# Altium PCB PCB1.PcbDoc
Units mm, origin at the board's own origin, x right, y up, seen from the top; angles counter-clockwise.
Board outline 77.6 x 45.97 mm, 2 copper layers (Top Layer, Bottom Layer); 10 components, 6 nets, 87 pads, 0 vias.
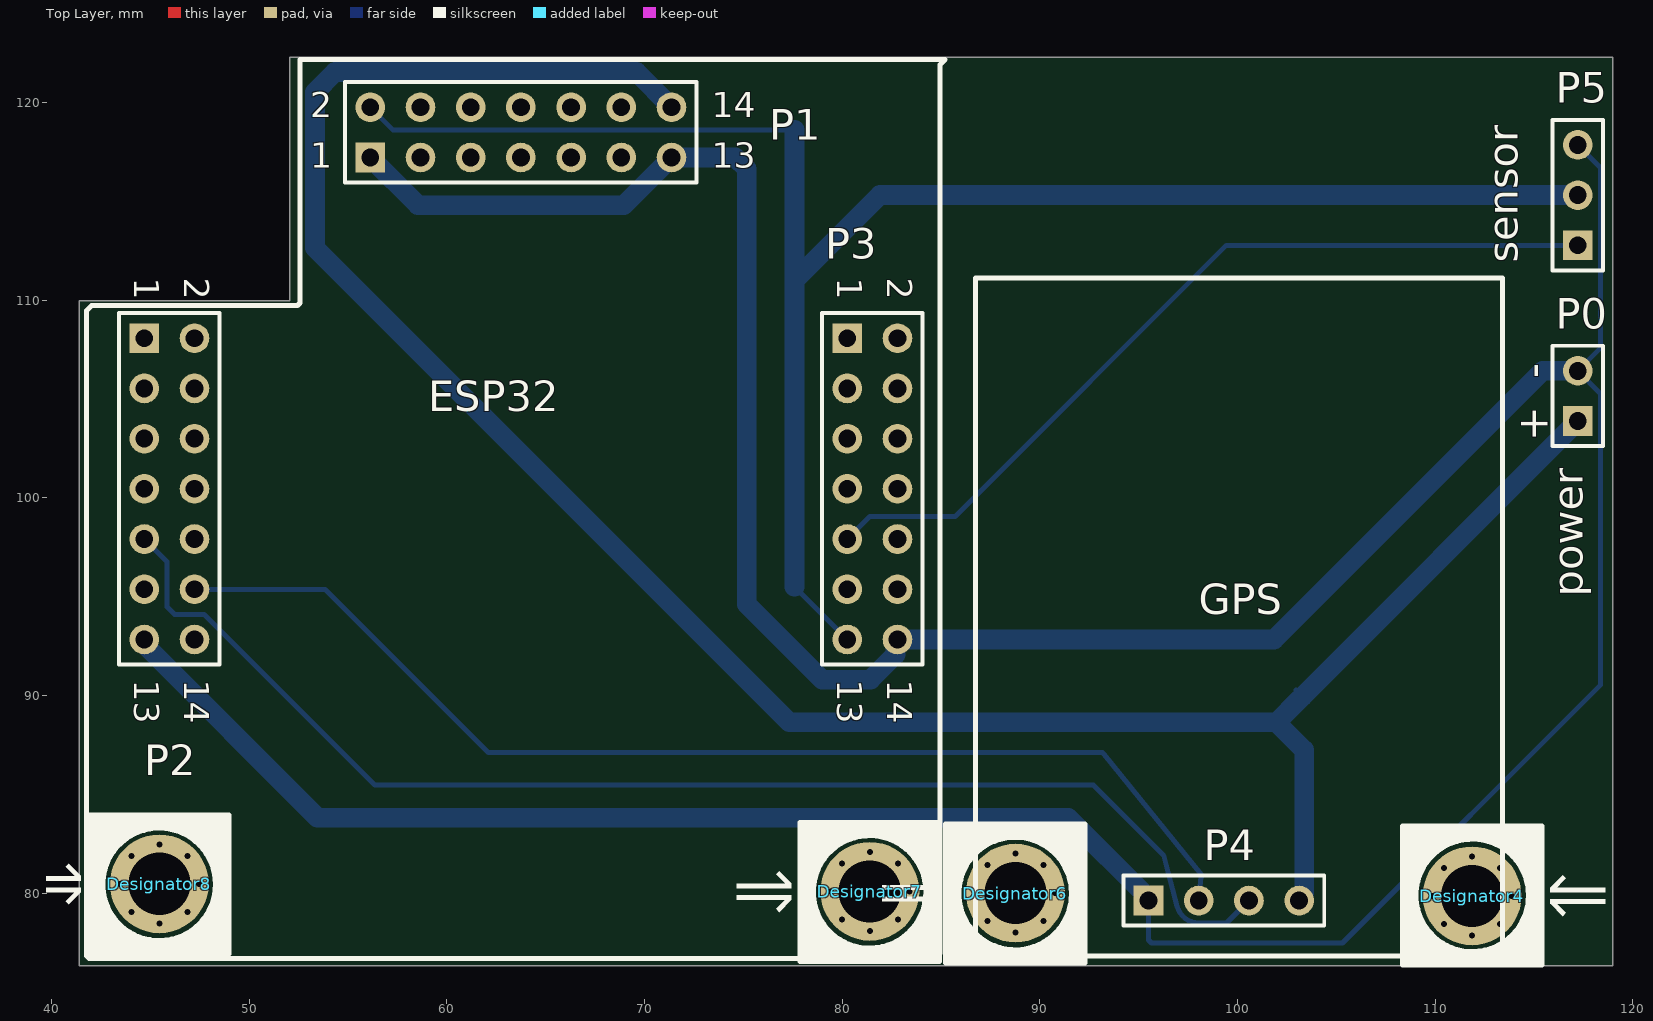
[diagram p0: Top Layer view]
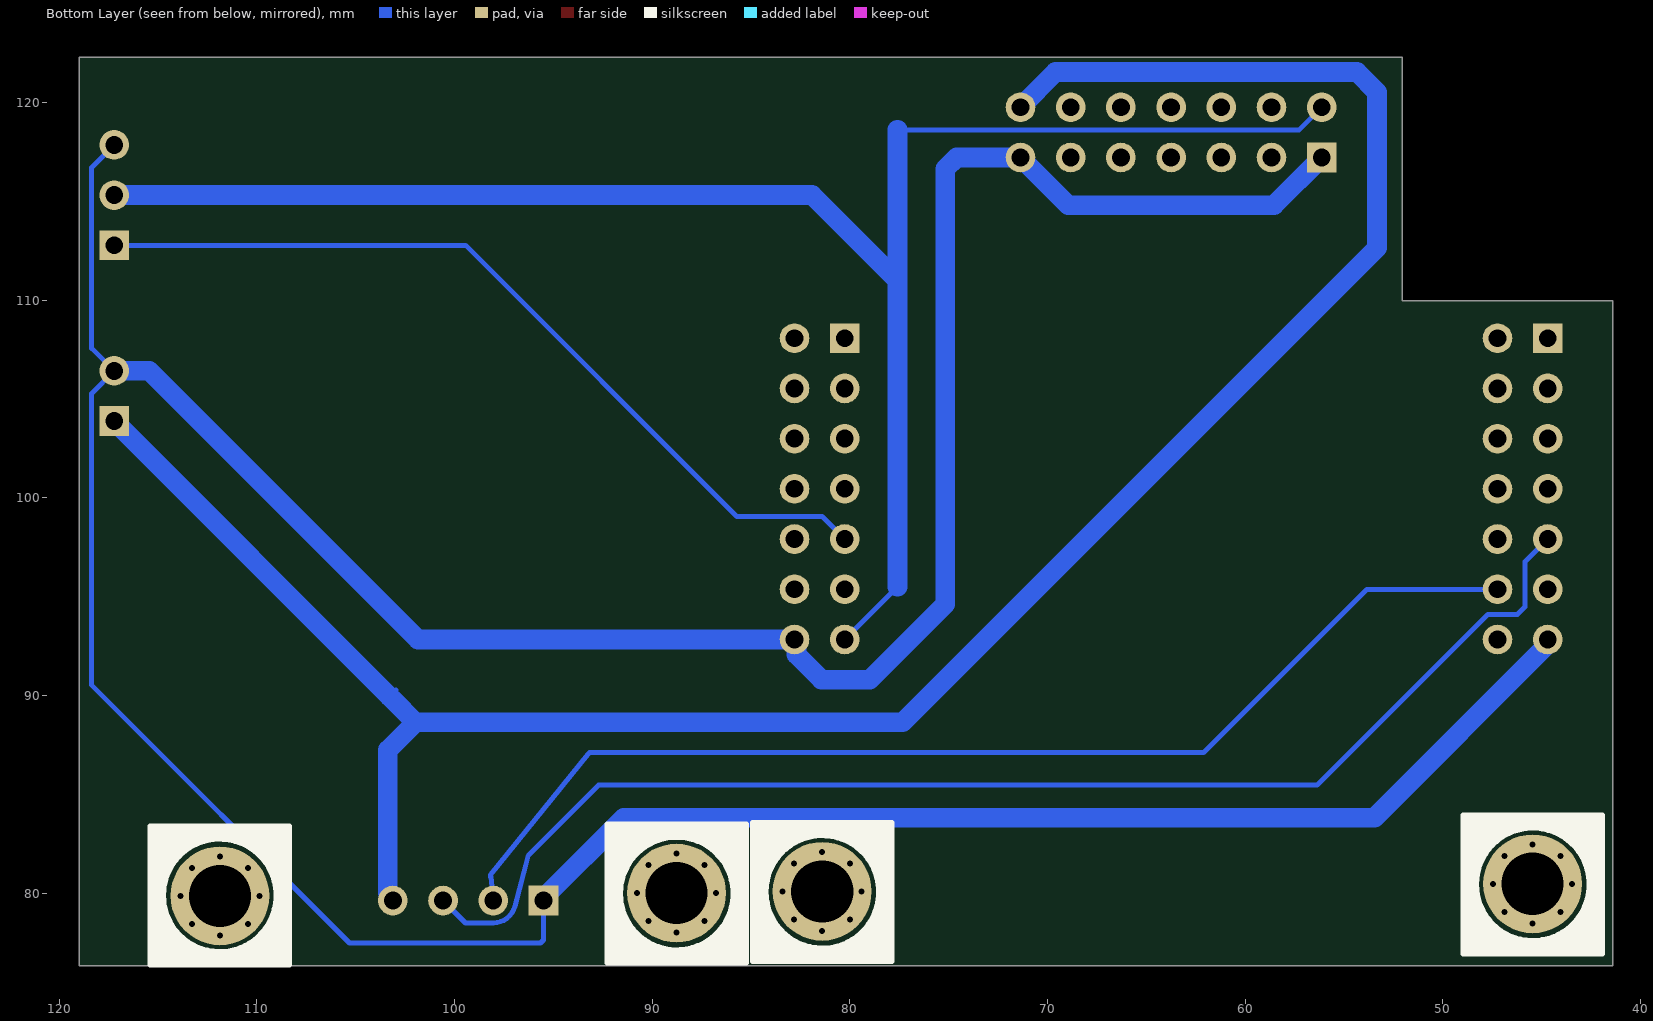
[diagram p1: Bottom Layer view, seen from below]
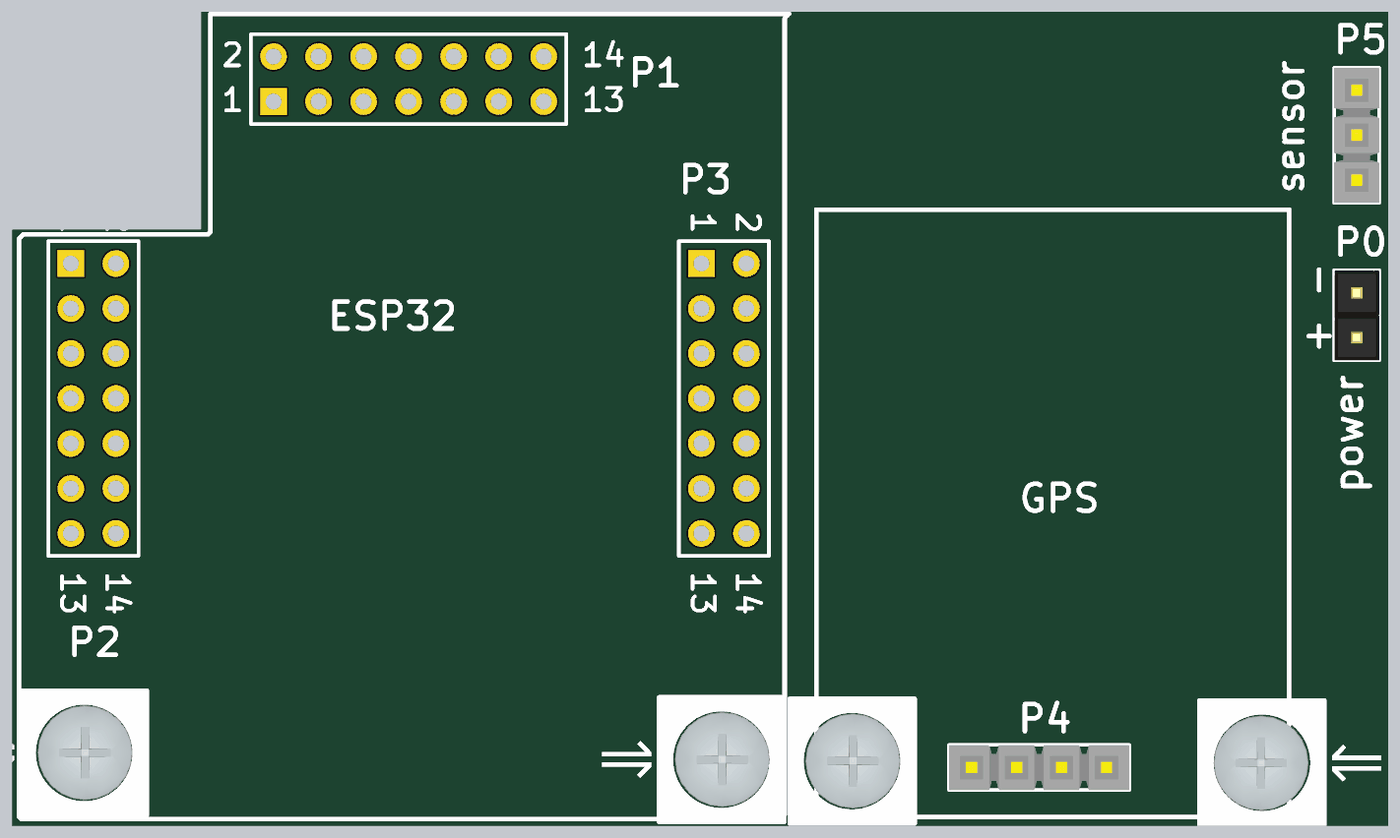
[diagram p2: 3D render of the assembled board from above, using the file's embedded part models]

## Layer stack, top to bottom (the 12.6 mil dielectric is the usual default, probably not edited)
Top Solder: solder mask 0.0102, Solder Resist, Dk 3.5
Top Layer: signal copper 0.0356
Dielectric 1: dielectric 0.32, FR-4, Dk 4.8
Bottom Layer: signal copper 0.0356
Bottom Solder: solder mask 0.0102, Solder Resist, Dk 3.5

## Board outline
41.402,76.327 41.402,109.982 52.07,109.982 52.07,122.301 118.999,122.301 118.999,76.327

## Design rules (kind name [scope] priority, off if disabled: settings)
Clearance [All] p1: gap=0.254 ignorepadtopadclearanceinfootprint=FALSE
PolygonConnect [All] p1: connectstyle=Relief reliefconductorwidth=0.254 reliefentries=4 polygonreliefangle="90 Angle" airgapwidth=0.254
RoutingVias [All] p1: holewidth=0.711 width=1.27 viastyle="Through Hole" minholewidth=0.711 minwidth=1.27 maxholewidth=0.711 maxwidth=1.27
SolderMaskExpansion [All] p1: expansion=0.102 istentingtop=FALSE
SupplyNets "Schematic Supply Nets_2" [InNet('VCC')] p1: voltage=0.000
SupplyNets "Schematic Supply Nets_1" [InNet('GND')] p2: voltage=0.000
SupplyNets "Schematic Supply Nets" [InNet('3.3v')] p3: voltage=0.000
Width [All] p1: maxlimit=2 minlimit=0.254 preferedwidth=1 minimp=50.000000 maximp=50.000000 favimp=50.000000
30 further rules are at their usual default settings.

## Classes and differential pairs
component class Sheet1: P0 P1 P2 P3 P4 P5

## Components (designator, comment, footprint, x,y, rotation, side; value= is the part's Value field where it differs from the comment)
Designator4 "Comment" "Board Screw" 111.87,79.866 r90 top
Designator6 "Comment" "Board Screw" 88.773,80.01 r270 top
Designator7 "Comment" "Board Screw" 81.407,80.093 r270 top
Designator8 "Comment" "Board Screw" 45.466,80.474 r270 top
P0 "Header 2" HDR1X2 117.221,103.886 r90 top
P1 "Header 7X2" HDR2X7 56.134,117.221 r0 top
P2 "Header 7X2" HDR2X7 44.704,108.077 r270 top
P3 "Header 7X2" HDR2X7 80.264,108.077 r270 top
P4 "Header 4" HDR1X4 95.504,79.629 r0 top
P5 "Header 3" HDR1X3 117.221,112.776 r90 top

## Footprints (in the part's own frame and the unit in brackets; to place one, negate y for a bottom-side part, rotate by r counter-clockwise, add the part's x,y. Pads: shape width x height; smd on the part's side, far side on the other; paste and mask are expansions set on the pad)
"Board Screw" [mm]
  round 0.6 hole 0.3: S(-2,0) S(-1.414,-1.414) S(-1.414,1.414) S(0,2) S(0,-2) S(1.414,-1.414) S(1.414,1.414) S(2,0)
  round 5 hole 3.15 mask+0.1: S(0,0)
  silkscreen extent -3.49,-6.75 3.56,3.52, body extent -2.67,-2.64 2.69,2.72, height 2.34
HDR1X2 [mm] "Connector; Header; 2 Position"
  rect 1.5x1.5 hole 0.9: 1(0,0)
  round 1.5 hole 0.9: 2(2.54,0)
  silkscreen extent -1.27,-1.27 3.81,1.27, body extent -1.27,-1.28 3.81,1.26, height 8.79
HDR1X3 [mm] "Connector; Header; 3 Position"
  rect 1.5x1.5 hole 0.9: 1(0,0)
  round 1.5 hole 0.9: 2(2.54,0) 3(5.08,0)
  silkscreen extent -1.27,-1.27 6.35,1.27, body extent -1.26,-1.27 6.36,1.27, height 8.38
HDR1X4 [mm] "Connector; Header; 4 Position"
  rect 1.5x1.5 hole 0.9: 1(0,0)
  round 1.5 hole 0.9: 2(2.54,0) 3(5.08,0) 4(7.62,0)
  silkscreen extent -1.27,-1.27 8.89,1.27, body extent -1.27,-1.28 8.89,1.26, height 8.38
HDR2X7 [mm] "Connector; Header; 7x2 Position"
  rect 1.5x1.5 hole 0.9: 1(0,0)
  round 1.5 hole 0.9: 2(0,2.54) 3(2.54,0) 4(2.54,2.54) 5(5.08,0) 6(5.08,2.54) 7(7.62,0) 8(7.62,2.54) 9(10.16,0) 10(10.16,2.54) 11(12.7,0) 12(12.7,2.54) 13(15.24,0) 14(15.24,2.54)
  silkscreen extent -1.27,-1.27 16.51,3.81

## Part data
P0: "Header, 2-Pin"
P1 P2 P3: "Header, 7-Pin, Dual row"
P4: "Header, 4-Pin"
P5: "Header, 3-Pin"

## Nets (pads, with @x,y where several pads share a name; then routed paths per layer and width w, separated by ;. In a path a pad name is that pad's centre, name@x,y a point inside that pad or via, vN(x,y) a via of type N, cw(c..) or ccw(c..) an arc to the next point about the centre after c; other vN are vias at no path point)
3.3v: P1.2 P3.13 P5.2 | length 97.9
  Bottom Layer w0.254: P1.2 57.277,118.618 77.597,118.618 77.597,110.998 ; 77.597,95.504 P3.13
  Bottom Layer w1: 77.597,95.504 77.597,110.998 ; 77.597,118.618 77.597,110.998 ; P5.2 81.915,115.316 77.597,110.998
GND: P0.2 P1.1 P1.13 P2.13 P3.14 P4.1 P5.3 | length 211.3
  Bottom Layer w0.254: P2.13@44.704,92.587 P2.13 ; 95.504,77.724 P4.1@95.504,79.756 ; P4.1 95.504,77.631 95.653,77.482 105.32,77.482 118.364,90.526 118.364,105.283 P0.2 118.364,107.569 118.364,116.713 P5.3
  Bottom Layer w1: P2.13@44.704,92.587 53.471,83.82 91.44,83.82 P4.1@95.504,79.756 ; P1.1 58.547,114.808 68.961,114.808 P1.13 74.598,117.221 75.184,116.635 75.184,94.615 78.994,90.805 81.44,90.805 82.708,92.073 82.708,92.741 P3.14 101.854,92.837 115.443,106.426 P0.2
rx: P2.12 P4.2 | length 58.6
  Bottom Layer w0.254: P2.12 53.848,95.377 62.109,87.116 93.171,87.116 93.255,87.032 98.173,80.928 98.173,80.825 98.171,80.812 P4.2
"signal finger": P3.9 P5.1 | length 43.1
  Bottom Layer w0.254: P3.9 81.407,99.06 85.725,99.06 99.441,112.776 P5.1
tx: P2.9 P4.3 | length 66.7
  Bottom Layer w0.254: P2.9 45.847,96.774 45.847,94.488 46.228,94.107 47.727,94.107 56.363,85.471 92.71,85.471 96.274,81.907 96.95,79.341 ccw(c98.044,79.629) 98.044,78.498 99.453,78.498 P4.3
VCC: P0.1 P1.14 P4.4 | length 117.4
  Bottom Layer w0.254: 102.975,90.272 103.124,90.123 103.124,89.789
  Bottom Layer w1: P1.14 69.596,121.539 54.356,121.539 53.34,120.523 53.34,112.649 77.343,88.646 101.981,88.646 ; P4.4 103.124,79.764 103.378,80.018 103.378,87.249 101.981,88.646 ; P0.1 103.291,89.956 103.124,89.789 101.981,88.646
pads on no net: Designator4.S Designator6.S Designator7.S Designator8.S P1.3 P1.4 P1.5 P1.6 P1.7 P1.8 P1.9 P1.10 P1.11 P1.12 P2.1 P2.2 P2.3 P2.4 P2.5 P2.6 P2.7 P2.8 P2.10 P2.11 P2.14 P3.1 P3.2 P3.3 P3.4 P3.5 P3.6 P3.7 P3.8 P3.10 P3.11 P3.12

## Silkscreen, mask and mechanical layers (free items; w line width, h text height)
Top Overlay:
  lines w0.254: 41.783,76.835 41.783,109.474 42.037,109.728 52.451,109.728 52.578,109.855 52.578,122.174 85.217,122.174 84.963,121.92 84.963,76.962 84.709,76.708 41.91,76.708 41.783,76.835 ; 86.741,76.835 113.411,76.835 113.411,111.125 86.741,111.125 86.741,76.835
  text "sensor" at 114.173,111.887 h1.52 r90
  text "-" at 115.697,106.045 h1.52 r90
  text "ESP32" at 59.055,104.394 h1.52
  text "+" at 115.697,102.87 h1.52 r90
  text "power" at 117.475,94.996 h1.52 r90
  text "GPS" at 98.044,94.107 h1.52
Mechanical 1:
  the board outline again, w0.254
